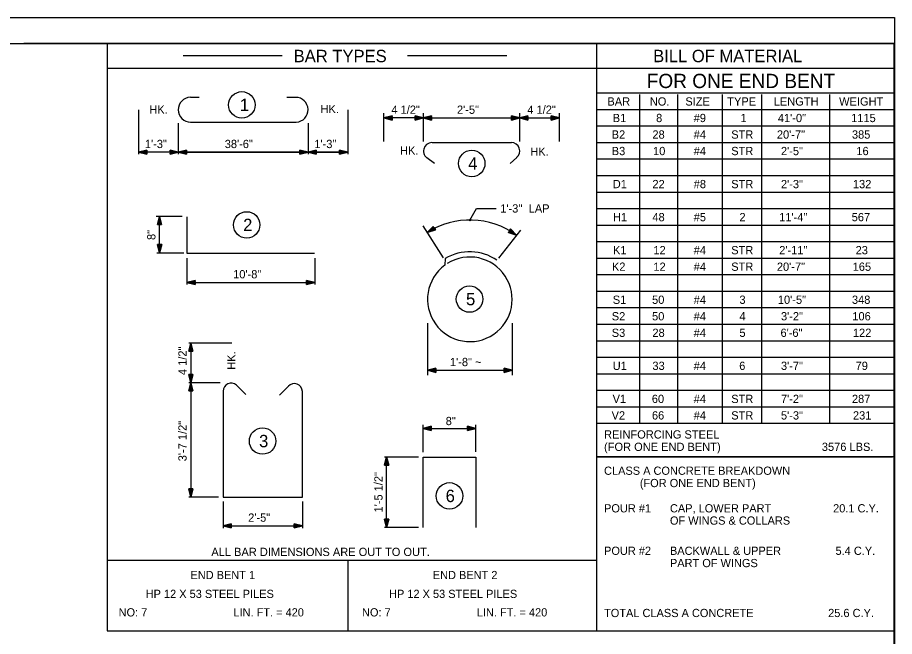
# Model space of a CAD drawing. Extents: x -41 to 251, y -169 to 237.
# Drawn here: x 45.29 to 75.65, y -139.61 to -118.18 of the extents above; entities that cross this region are included whole.
import ezdxf

# ---------------------------------------------------------------- set-up
doc = ezdxf.new("R2010")
doc.units = 0
for name, color, linetype in [('Dimension Lines CELL', 7, 'Continuous'), ('Plan Sheet CELL', 7, 'Continuous'), ('Plot Shape CELL', 7, 'Continuous'), ('Rebar Lines CELL', 7, 'Continuous'), ('Subtitle Text', 7, 'Continuous'), ('Text', 7, 'Continuous'), ('Text CELL', 7, 'Continuous')]:
    doc.layers.add(name, color=color, linetype=linetype)

msp = doc.modelspace()

# ---------------------------------------------------------------- linework, layer by layer
at = {"layer": 'Dimension Lines CELL'}
for p, q in [((49.476, -121.372), (49.476, -122.914)), ((56.718, -121.372), (56.718, -122.914)), ((57.969, -122.469), (57.969, -121.491)), ((59.336, -121.656), (57.969, -121.656)), ((59.336, -121.656), (62.673, -121.656)), ((59.342, -122.469), (59.342, -121.491)), ((62.673, -122.469), (62.673, -121.491)), ((62.673, -121.656), (64.046, -121.656)), ((64.046, -122.469), (64.046, -121.491)), ((50.849, -121.84), (50.849, -122.914)), ((55.345, -121.84), (55.345, -122.914)), ((50.853, -122.842), (49.476, -122.842)), ((50.853, -122.842), (55.345, -122.842)), ((56.489, -122.842), (50.853, -122.842)), ((55.345, -122.842), (56.718, -122.842)), ((50.983, -125.063), (50.087, -125.064)), ((50.205, -126.327), (50.204, -125.064)), ((60.947, -125.19), (61.175, -124.793)), ((61.175, -124.793), (61.862, -124.793)), ((60.031, -126.493), (59.334, -125.395)), ((62.699, -125.545), (61.939, -126.515)), ((50.107, -126.327), (51.045, -126.326)), ((51.146, -126.511), (51.146, -127.423)), ((55.576, -126.511), (55.576, -127.423)), ((51.146, -127.352), (55.576, -127.352)), ((59.482, -128.766), (59.482, -130.56)), ((62.411, -128.766), (62.411, -130.56)), ((52.707, -129.449), (51.213, -129.449)), ((51.284, -129.449), (51.284, -130.822)), ((59.487, -130.391), (62.416, -130.391)), ((52.308, -130.822), (51.213, -130.822)), ((51.284, -130.822), (51.284, -134.786)), ((59.327, -133.224), (59.327, -132.281)), ((61.157, -133.216), (61.157, -132.281)), ((59.327, -132.402), (61.157, -132.402)), ((59.174, -133.399), (57.995, -133.399)), ((58.067, -135.831), (58.067, -133.399)), ((52.25, -134.786), (51.213, -134.786)), ((52.403, -134.939), (52.403, -135.854)), ((55.148, -134.939), (55.148, -135.854)), ((52.403, -135.778), (55.148, -135.778)), ((59.174, -135.837), (57.995, -135.837))]:
    msp.add_line(p, q, dxfattribs=at)
for points in [[(58.255, -121.656), (58.255, -121.67), (57.969, -121.656), (58.255, -121.685), (58.255, -121.699), (57.969, -121.656), (58.255, -121.713), (58.255, -121.728), (57.969, -121.656), (58.255, -121.585), (58.255, -121.599), (57.969, -121.656), (58.255, -121.613), (58.255, -121.627), (57.969, -121.656), (58.255, -121.642), (58.255, -121.728), (58.255, -121.585), (57.969, -121.656), (58.255, -121.728)], [(59.05, -121.656), (59.05, -121.642), (59.336, -121.656), (59.05, -121.627), (59.05, -121.613), (59.336, -121.656), (59.05, -121.599), (59.05, -121.585), (59.336, -121.656), (59.05, -121.728), (59.05, -121.713), (59.336, -121.656), (59.05, -121.699), (59.05, -121.685), (59.336, -121.656), (59.05, -121.67), (59.05, -121.585), (59.05, -121.728), (59.336, -121.656), (59.05, -121.585)], [(59.622, -121.656), (59.622, -121.67), (59.336, -121.656), (59.622, -121.685), (59.622, -121.699), (59.336, -121.656), (59.622, -121.713), (59.622, -121.728), (59.336, -121.656), (59.622, -121.585), (59.622, -121.599), (59.336, -121.656), (59.622, -121.613), (59.622, -121.627), (59.336, -121.656), (59.622, -121.642), (59.622, -121.728), (59.622, -121.585), (59.336, -121.656), (59.622, -121.728)], [(62.387, -121.656), (62.387, -121.642), (62.673, -121.656), (62.387, -121.627), (62.387, -121.613), (62.673, -121.656), (62.387, -121.599), (62.387, -121.585), (62.673, -121.656), (62.387, -121.728), (62.387, -121.713), (62.673, -121.656), (62.387, -121.699), (62.387, -121.685), (62.673, -121.656), (62.387, -121.67), (62.387, -121.585), (62.387, -121.728), (62.673, -121.656), (62.387, -121.585)], [(62.959, -121.656), (62.959, -121.67), (62.673, -121.656), (62.959, -121.685), (62.959, -121.699), (62.673, -121.656), (62.959, -121.713), (62.959, -121.728), (62.673, -121.656), (62.959, -121.585), (62.959, -121.599), (62.673, -121.656), (62.959, -121.613), (62.959, -121.627), (62.673, -121.656), (62.959, -121.642), (62.959, -121.728), (62.959, -121.585), (62.673, -121.656), (62.959, -121.728)], [(63.76, -121.656), (63.76, -121.642), (64.046, -121.656), (63.76, -121.627), (63.76, -121.613), (64.046, -121.656), (63.76, -121.599), (63.76, -121.585), (64.046, -121.656), (63.76, -121.728), (63.76, -121.713), (64.046, -121.656), (63.76, -121.699), (63.76, -121.685), (64.046, -121.656), (63.76, -121.67), (63.76, -121.585), (63.76, -121.728), (64.046, -121.656), (63.76, -121.585)], [(49.762, -122.842), (49.762, -122.857), (49.476, -122.842), (49.762, -122.871), (49.762, -122.885), (49.476, -122.842), (49.762, -122.9), (49.762, -122.914), (49.476, -122.842), (49.762, -122.771), (49.762, -122.785), (49.476, -122.842), (49.762, -122.799), (49.762, -122.814), (49.476, -122.842), (49.762, -122.828), (49.762, -122.914), (49.762, -122.771), (49.476, -122.842), (49.762, -122.914)], [(50.567, -122.842), (50.567, -122.828), (50.853, -122.842), (50.567, -122.814), (50.567, -122.799), (50.853, -122.842), (50.567, -122.785), (50.567, -122.771), (50.853, -122.842), (50.567, -122.914), (50.567, -122.9), (50.853, -122.842), (50.567, -122.885), (50.567, -122.871), (50.853, -122.842), (50.567, -122.857), (50.567, -122.771), (50.567, -122.914), (50.853, -122.842), (50.567, -122.771)], [(51.139, -122.842), (51.139, -122.857), (50.853, -122.842), (51.139, -122.871), (51.139, -122.885), (50.853, -122.842), (51.139, -122.9), (51.139, -122.914), (50.853, -122.842), (51.139, -122.771), (51.139, -122.785), (50.853, -122.842), (51.139, -122.799), (51.139, -122.814), (50.853, -122.842), (51.139, -122.828), (51.139, -122.914), (51.139, -122.771), (50.853, -122.842), (51.139, -122.914)], [(55.059, -122.842), (55.059, -122.828), (55.345, -122.842), (55.059, -122.814), (55.059, -122.799), (55.345, -122.842), (55.059, -122.785), (55.059, -122.771), (55.345, -122.842), (55.059, -122.914), (55.059, -122.9), (55.345, -122.842), (55.059, -122.885), (55.059, -122.871), (55.345, -122.842), (55.059, -122.857), (55.059, -122.771), (55.059, -122.914), (55.345, -122.842), (55.059, -122.771)], [(55.631, -122.842), (55.631, -122.857), (55.345, -122.842), (55.631, -122.871), (55.631, -122.885), (55.345, -122.842), (55.631, -122.9), (55.631, -122.914), (55.345, -122.842), (55.631, -122.771), (55.631, -122.785), (55.345, -122.842), (55.631, -122.799), (55.631, -122.814), (55.345, -122.842), (55.631, -122.828), (55.631, -122.914), (55.631, -122.771), (55.345, -122.842), (55.631, -122.914)], [(56.432, -122.842), (56.432, -122.828), (56.718, -122.842), (56.432, -122.814), (56.432, -122.799), (56.718, -122.842), (56.432, -122.785), (56.432, -122.771), (56.718, -122.842), (56.432, -122.914), (56.432, -122.9), (56.718, -122.842), (56.432, -122.885), (56.432, -122.871), (56.718, -122.842), (56.432, -122.857), (56.432, -122.771), (56.432, -122.914), (56.718, -122.842), (56.432, -122.771)], [(50.204, -125.35), (50.19, -125.35), (50.204, -125.064), (50.176, -125.35), (50.161, -125.35), (50.204, -125.064), (50.147, -125.35), (50.133, -125.35), (50.204, -125.064), (50.276, -125.35), (50.262, -125.35), (50.204, -125.064), (50.247, -125.35), (50.233, -125.35), (50.204, -125.064), (50.219, -125.35), (50.133, -125.35), (50.276, -125.35), (50.204, -125.064), (50.133, -125.35)], [(59.718, -125.47), (59.726, -125.482), (59.474, -125.618), (59.733, -125.495), (59.74, -125.507), (59.474, -125.618), (59.748, -125.519), (59.755, -125.531), (59.474, -125.618), (59.681, -125.409), (59.689, -125.421), (59.474, -125.618), (59.696, -125.433), (59.703, -125.446), (59.474, -125.618), (59.711, -125.458), (59.755, -125.531), (59.681, -125.409), (59.474, -125.618), (59.755, -125.531)], [(62.321, -125.558), (62.328, -125.546), (62.56, -125.714), (62.336, -125.534), (62.344, -125.522), (62.56, -125.714), (62.352, -125.51), (62.359, -125.498), (62.56, -125.714), (62.282, -125.618), (62.289, -125.606), (62.56, -125.714), (62.297, -125.594), (62.305, -125.582), (62.56, -125.714), (62.313, -125.57), (62.359, -125.498), (62.282, -125.618), (62.56, -125.714), (62.359, -125.498)], [(50.205, -126.041), (50.219, -126.041), (50.205, -126.327), (50.234, -126.041), (50.248, -126.041), (50.205, -126.327), (50.262, -126.041), (50.277, -126.041), (50.205, -126.327), (50.133, -126.041), (50.148, -126.041), (50.205, -126.327), (50.162, -126.041), (50.176, -126.041), (50.205, -126.327), (50.191, -126.041), (50.277, -126.041), (50.133, -126.041), (50.205, -126.327), (50.277, -126.041)], [(51.432, -127.352), (51.432, -127.366), (51.146, -127.352), (51.432, -127.38), (51.432, -127.395), (51.146, -127.352), (51.432, -127.409), (51.432, -127.423), (51.146, -127.352), (51.432, -127.28), (51.432, -127.295), (51.146, -127.352), (51.432, -127.309), (51.432, -127.323), (51.146, -127.352), (51.432, -127.338), (51.432, -127.423), (51.432, -127.28), (51.146, -127.352), (51.432, -127.423)], [(55.29, -127.352), (55.29, -127.338), (55.576, -127.352), (55.29, -127.323), (55.29, -127.309), (55.576, -127.352), (55.29, -127.295), (55.29, -127.28), (55.576, -127.352), (55.29, -127.423), (55.29, -127.409), (55.576, -127.352), (55.29, -127.395), (55.29, -127.38), (55.576, -127.352), (55.29, -127.366), (55.29, -127.28), (55.29, -127.423), (55.576, -127.352), (55.29, -127.28)], [(51.284, -129.735), (51.27, -129.735), (51.284, -129.449), (51.256, -129.735), (51.241, -129.735), (51.284, -129.449), (51.227, -129.735), (51.213, -129.735), (51.284, -129.449), (51.356, -129.735), (51.341, -129.735), (51.284, -129.449), (51.327, -129.735), (51.313, -129.735), (51.284, -129.449), (51.299, -129.735), (51.213, -129.735), (51.356, -129.735), (51.284, -129.449), (51.213, -129.735)], [(51.284, -130.536), (51.299, -130.536), (51.284, -130.822), (51.313, -130.536), (51.327, -130.536), (51.284, -130.822), (51.341, -130.536), (51.356, -130.536), (51.284, -130.822), (51.213, -130.536), (51.227, -130.536), (51.284, -130.822), (51.241, -130.536), (51.256, -130.536), (51.284, -130.822), (51.27, -130.536), (51.356, -130.536), (51.213, -130.536), (51.284, -130.822), (51.356, -130.536)], [(59.773, -130.391), (59.773, -130.406), (59.487, -130.391), (59.773, -130.42), (59.773, -130.434), (59.487, -130.391), (59.773, -130.449), (59.773, -130.463), (59.487, -130.391), (59.773, -130.32), (59.773, -130.334), (59.487, -130.391), (59.773, -130.348), (59.773, -130.363), (59.487, -130.391), (59.773, -130.377), (59.773, -130.463), (59.773, -130.32), (59.487, -130.391), (59.773, -130.463)], [(62.13, -130.391), (62.13, -130.377), (62.416, -130.391), (62.13, -130.363), (62.13, -130.348), (62.416, -130.391), (62.13, -130.334), (62.13, -130.32), (62.416, -130.391), (62.13, -130.463), (62.13, -130.449), (62.416, -130.391), (62.13, -130.434), (62.13, -130.42), (62.416, -130.391), (62.13, -130.406), (62.13, -130.32), (62.13, -130.463), (62.416, -130.391), (62.13, -130.32)], [(51.284, -131.108), (51.27, -131.108), (51.284, -130.822), (51.256, -131.108), (51.241, -131.108), (51.284, -130.822), (51.227, -131.108), (51.213, -131.108), (51.284, -130.822), (51.356, -131.108), (51.341, -131.108), (51.284, -130.822), (51.327, -131.108), (51.313, -131.108), (51.284, -130.822), (51.299, -131.108), (51.213, -131.108), (51.356, -131.108), (51.284, -130.822), (51.213, -131.108)], [(59.613, -132.402), (59.613, -132.416), (59.327, -132.402), (59.613, -132.43), (59.613, -132.444), (59.327, -132.402), (59.613, -132.459), (59.613, -132.473), (59.327, -132.402), (59.613, -132.33), (59.613, -132.344), (59.327, -132.402), (59.613, -132.359), (59.613, -132.373), (59.327, -132.402), (59.613, -132.387), (59.613, -132.473), (59.613, -132.33), (59.327, -132.402), (59.613, -132.473)], [(60.871, -132.402), (60.871, -132.387), (61.157, -132.402), (60.871, -132.373), (60.871, -132.359), (61.157, -132.402), (60.871, -132.344), (60.871, -132.33), (61.157, -132.402), (60.871, -132.473), (60.871, -132.459), (61.157, -132.402), (60.871, -132.444), (60.871, -132.43), (61.157, -132.402), (60.871, -132.416), (60.871, -132.33), (60.871, -132.473), (61.157, -132.402), (60.871, -132.33)], [(58.067, -133.676), (58.052, -133.676), (58.067, -133.39), (58.038, -133.676), (58.024, -133.676), (58.067, -133.39), (58.009, -133.676), (57.995, -133.676), (58.067, -133.39), (58.138, -133.676), (58.124, -133.676), (58.067, -133.39), (58.109, -133.676), (58.095, -133.676), (58.067, -133.39), (58.081, -133.676), (57.995, -133.676), (58.138, -133.676), (58.067, -133.39), (57.995, -133.676)], [(51.284, -134.5), (51.299, -134.5), (51.284, -134.786), (51.313, -134.5), (51.327, -134.5), (51.284, -134.786), (51.341, -134.5), (51.356, -134.5), (51.284, -134.786), (51.213, -134.5), (51.227, -134.5), (51.284, -134.786), (51.241, -134.5), (51.256, -134.5), (51.284, -134.786), (51.27, -134.5), (51.356, -134.5), (51.213, -134.5), (51.284, -134.786), (51.356, -134.5)], [(52.689, -135.778), (52.689, -135.792), (52.403, -135.778), (52.689, -135.806), (52.689, -135.821), (52.403, -135.778), (52.689, -135.835), (52.689, -135.849), (52.403, -135.778), (52.689, -135.706), (52.689, -135.72), (52.403, -135.778), (52.689, -135.735), (52.689, -135.749), (52.403, -135.778), (52.689, -135.763), (52.689, -135.849), (52.689, -135.706), (52.403, -135.778), (52.689, -135.849)], [(54.862, -135.778), (54.862, -135.763), (55.148, -135.778), (54.862, -135.749), (54.862, -135.735), (55.148, -135.778), (54.862, -135.72), (54.862, -135.706), (55.148, -135.778), (54.862, -135.849), (54.862, -135.835), (55.148, -135.778), (54.862, -135.821), (54.862, -135.806), (55.148, -135.778), (54.862, -135.792), (54.862, -135.706), (54.862, -135.849), (55.148, -135.778), (54.862, -135.706)], [(58.067, -135.545), (58.081, -135.545), (58.067, -135.831), (58.095, -135.545), (58.109, -135.545), (58.067, -135.831), (58.124, -135.545), (58.138, -135.545), (58.067, -135.831), (57.995, -135.545), (58.009, -135.545), (58.067, -135.831), (58.024, -135.545), (58.038, -135.545), (58.067, -135.831), (58.052, -135.545), (58.138, -135.545), (57.995, -135.545), (58.067, -135.831), (58.138, -135.545)]]:
    msp.add_lwpolyline(points, dxfattribs=at)
for centre, radius in [((53.053, -121.203), 0.458), ((61.012, -123.232), 0.458), ((53.22, -125.359), 0.458), ((60.948, -125.19), 0.0229), ((60.937, -127.926), 0.458), ((53.772, -132.841), 0.458), ((60.242, -134.74), 0.458)]:
    msp.add_circle(centre, radius, dxfattribs=at)
msp.add_arc((60.947, -127.935), 2.746, 54.0023, 122.4453, dxfattribs=at)
at = {"layer": 'Plan Sheet CELL'}
for p, q in [((75.648, -118.18), (75.648, -118.18)), ((2.412, -119.081), (75.628, -119.081)), ((75.628, -119.081), (45.504, -119.081)), ((48.387, -119.081), (48.387, -139.408)), ((65.332, -119.081), (65.332, -139.408)), ((75.628, -119.081), (75.628, -167.129)), ((75.628, -119.081), (75.628, -137.959)), ((54.448, -119.51), (51.016, -119.51)), ((62.224, -119.51), (58.792, -119.51)), ((65.332, -119.94), (48.387, -119.94)), ((75.628, -119.94), (65.332, -119.94)), ((75.628, -120.799), (65.332, -120.799)), ((66.82, -120.843), (66.82, -132.239)), ((68.135, -120.843), (68.135, -132.239)), ((69.68, -120.843), (69.68, -132.239)), ((71.044, -120.843), (71.044, -132.239)), ((73.399, -120.843), (73.399, -132.239)), ((75.628, -121.371), (65.332, -121.371)), ((75.628, -121.943), (65.332, -121.943)), ((75.628, -122.515), (65.332, -122.515)), ((75.628, -123.087), (65.332, -123.087)), ((75.628, -123.659), (65.332, -123.659)), ((75.628, -124.231), (65.332, -124.231)), ((75.628, -124.803), (65.332, -124.803)), ((75.628, -125.375), (65.332, -125.375)), ((75.628, -125.947), (65.332, -125.947)), ((75.628, -126.519), (65.332, -126.519)), ((75.628, -127.091), (65.332, -127.091)), ((75.628, -127.663), (65.332, -127.663)), ((75.628, -128.235), (65.332, -128.235)), ((75.628, -128.807), (65.332, -128.807)), ((75.628, -129.379), (65.332, -129.379)), ((75.628, -129.951), (65.332, -129.951)), ((75.628, -130.523), (65.332, -130.523)), ((75.628, -131.095), (65.332, -131.095)), ((75.628, -131.667), (65.332, -131.667)), ((75.628, -132.239), (65.332, -132.239)), ((75.628, -133.383), (65.332, -133.383)), ((65.332, -133.383), (75.577, -133.383)), ((48.4, -136.965), (65.332, -136.965)), ((48.4, -136.965), (64.128, -136.965)), ((56.727, -136.965), (56.727, -139.408)), ((48.387, -139.408), (75.648, -139.408))]:
    msp.add_line(p, q, dxfattribs=at)
at = {"layer": 'Plot Shape CELL'}
msp.add_lwpolyline([(0, -118.18), (75.648, -118.18), (75.648, -168.516), (0, -168.516)], close=True, dxfattribs=at)
at = {"layer": 'Rebar Lines CELL'}
for p, q in [((51.271, -120.942), (51.576, -120.942)), ((54.916, -120.943), (54.611, -120.943)), ((51.278, -121.8), (54.939, -121.8)), ((59.639, -122.504), (62.384, -122.504)), ((59.722, -123.236), (59.46, -123.038)), ((62.34, -123.236), (62.576, -123.02)), ((51.144, -125.075), (51.144, -126.338)), ((51.144, -126.338), (55.574, -126.338)), ((60.095, -126.525), (60.079, -126.755)), ((53.19, -131.233), (52.865, -130.908)), ((54.666, -130.944), (54.354, -131.256))]:
    msp.add_line(p, q, dxfattribs=at)
for points in [[(52.403, -131.116), (52.403, -134.786), (55.148, -134.786), (55.148, -131.121)], [(59.327, -135.837), (59.327, -133.397), (61.157, -133.397), (61.157, -135.837)]]:
    msp.add_lwpolyline(points, dxfattribs=at)
for centre, radius, start, end in [((51.278, -121.371), 0.429, 90.9575, 270), ((54.916, -121.372), 0.429, 272.972, 90), ((59.639, -122.801), 0.297, 91.6756, 242.6185), ((62.376, -122.801), 0.297, 309.3145, 88.3244), ((60.947, -127.935), 1.647, 55.2112, 121.1302), ((60.947, -127.935), 1.464, 126.3141, 122.4154), ((52.68, -131.116), 0.277, 48.347, 179.1529), ((54.872, -131.13), 0.277, 1.7953, 137.8717)]:
    msp.add_arc(centre, radius, start, end, dxfattribs=at)

# ---------------------------------------------------------------- texts
at = {"layer": 'Plan Sheet CELL'}
msp.add_text('BAR TYPES', height=0.429, dxfattribs=at).set_placement((54.848, -119.726))
at = {"layer": 'Subtitle Text'}
for s, height, p in [('BILL OF MATERIAL', 0.429, (67.294, -119.725)), ('FOR ONE END BENT', 0.49335, (67.071, -120.621)), ('1', 0.429, (52.985, -121.417)), ('4', 0.429, (60.89, -123.447)), ('2', 0.429, (53.098, -125.573)), ('5', 0.429, (60.815, -128.141)), ('3', 0.429, (53.65, -133.056)), ('6', 0.429, (60.109, -134.954))]:
    msp.add_text(s, height=height, dxfattribs=at).set_placement(p)
at = {"layer": 'Text'}
for s, height, p in [('BAR', 0.286, (65.71, -121.228)), ('NO.', 0.286, (67.178, -121.228)), ('SIZE', 0.286, (68.408, -121.228)), ('TYPE', 0.286, (69.859, -121.228)), ('LENGTH', 0.286, (71.469, -121.228)), ('WEIGHT', 0.286, (73.732, -121.228)), ('4 1/2"', 0.286, (58.23, -121.513)), ('2\'-5"', 0.286, (60.502, -121.513)), ('4 1/2"', 0.286, (62.937, -121.513)), ('B1', 0.286, (65.895, -121.8)), ('8', 0.286, (67.396, -121.8)), ('#9', 0.286, (68.697, -121.8)), ('1', 0.286, (70.317, -121.8)), ('41\'-0"', 0.286, (71.612, -121.8)), ('1115', 0.286, (74.149, -121.8)), ('B2', 0.286, (65.859, -122.372)), ('28', 0.286, (67.268, -122.372)), ('#4', 0.286, (68.698, -122.372)), ('STR', 0.286, (69.997, -122.372)), ('20\'-7"', 0.286, (71.578, -122.372)), ('385', 0.286, (74.176, -122.372)), ('1\'-3"', 0.286, (49.696, -122.699)), ('38\'-6"', 0.286, (52.461, -122.699)), ('1\'-3"', 0.286, (55.563, -122.699)), ('B3', 0.286, (65.859, -122.944)), ('10', 0.286, (67.289, -122.944)), ('#4', 0.286, (68.698, -122.944)), ('STR', 0.286, (69.997, -122.944)), ('2\'-5"', 0.286, (71.719, -122.944)), ('16', 0.286, (74.33, -122.944)), ('D1', 0.286, (65.895, -124.088)), ('22', 0.286, (67.268, -124.088)), ('#8', 0.286, (68.698, -124.088)), ('STR', 0.286, (69.997, -124.088)), ('2\'-3"', 0.286, (71.719, -124.088)), ('132', 0.286, (74.21, -124.088)), ('H1', 0.286, (65.903, -125.232)), ('48', 0.286, (67.268, -125.232)), ('#5', 0.286, (68.698, -125.232)), ('2', 0.286, (70.281, -125.232)), ('11\'-4"', 0.286, (71.658, -125.232)), ('567', 0.286, (74.168, -125.232)), ('K1', 0.286, (65.903, -126.376)), ('12', 0.286, (67.302, -126.376)), ('#4', 0.286, (68.698, -126.376)), ('STR', 0.286, (69.997, -126.376)), ('2\'-11"', 0.286, (71.658, -126.376)), ('23', 0.286, (74.304, -126.376)), ('K2', 0.286, (65.867, -126.948)), ('12', 0.286, (67.302, -126.948)), ('#4', 0.286, (68.698, -126.948)), ('STR', 0.286, (69.997, -126.948)), ('20\'-7"', 0.286, (71.578, -126.948)), ('165', 0.286, (74.202, -126.948)), ('10\'-8"', 0.286, (52.752, -127.209)), ('S1', 0.286, (65.896, -128.092)), ('50', 0.286, (67.256, -128.092)), ('#4', 0.286, (68.698, -128.092)), ('3', 0.286, (70.281, -128.092)), ('10\'-5"', 0.286, (71.612, -128.092)), ('348', 0.286, (74.176, -128.092)), ('S2', 0.286, (65.86, -128.664)), ('50', 0.286, (67.256, -128.664)), ('#4', 0.286, (68.698, -128.664)), ('4', 0.286, (70.281, -128.664)), ('3\'-2"', 0.286, (71.719, -128.664)), ('106', 0.286, (74.189, -128.664)), ('S3', 0.286, (65.86, -129.236)), ('28', 0.286, (67.268, -129.236)), ('#4', 0.286, (68.698, -129.236)), ('5', 0.286, (70.281, -129.236)), ('6\'-6"', 0.286, (71.703, -129.236)), ('122', 0.286, (74.21, -129.236)), ('1\'-8" ~', 0.286, (60.259, -130.248)), ('U1', 0.286, (65.894, -130.38)), ('33', 0.286, (67.268, -130.38)), ('#4', 0.286, (68.698, -130.38)), ('6', 0.286, (70.273, -130.38)), ('3\'-7"', 0.286, (71.719, -130.38)), ('79', 0.286, (74.303, -130.38)), ('V1', 0.286, (65.89, -131.524)), ('60', 0.286, (67.248, -131.524)), ('#4', 0.286, (68.698, -131.524)), ('STR', 0.286, (69.997, -131.524)), ('7\'-2"', 0.286, (71.719, -131.524)), ('287', 0.286, (74.176, -131.524)), ('8"', 0.286, (60.112, -132.291)), ('V2', 0.286, (65.854, -132.096)), ('66', 0.286, (67.252, -132.096)), ('#4', 0.286, (68.698, -132.096)), ('STR', 0.286, (69.997, -132.096)), ('5\'-3"', 0.286, (71.719, -132.096)), ('231', 0.286, (74.212, -132.096)), ('REINFORCING STEEL', 0.286, (65.594, -132.755)), ('(FOR ONE END BENT)', 0.286, (65.594, -133.184)), ('3576 LBS.', 0.286, (73.134, -133.184)), ('CLASS A CONCRETE BREAKDOWN', 0.28433, (65.594, -134.01)), ('(FOR ONE END BENT)', 0.28433, (66.832, -134.437)), ('POUR #1', 0.2843, (65.594, -135.312)), ('CAP, LOWER PART', 0.28433, (67.875, -135.312)), ('20.1 C.Y.', 0.2843, (73.524, -135.312)), ('2\'-5"', 0.286, (53.273, -135.635)), ('OF WINGS & COLLARS', 0.28433, (67.875, -135.736)), ('ALL BAR DIMENSIONS ARE OUT TO OUT.', 0.286, (51.997, -136.822)), ('POUR #2', 0.2843, (65.594, -136.782)), ('BACKWALL & UPPER', 0.28433, (67.875, -136.782)), ('5.4 C.Y.', 0.2843, (73.608, -136.782)), ('PART OF WINGS', 0.28433, (67.875, -137.207)), ('END BENT 1', 0.2843, (51.273, -137.622)), ('END BENT 2', 0.2843, (59.663, -137.622)), ('HP 12 X 53 STEEL PILES', 0.28433, (49.723, -138.274)), ('HP 12 X 53 STEEL PILES', 0.28433, (58.149, -138.274)), ('NO: 7', 0.2843, (48.787, -138.914)), ('LIN. FT. = 420', 0.28433, (52.761, -138.914)), ('NO: 7', 0.2843, (57.213, -138.914)), ('LIN. FT. = 420', 0.28433, (61.187, -138.914)), ('TOTAL CLASS A CONCRETE', 0.28433, (65.594, -138.936)), ('25.6 C.Y.', 0.2843, (73.353, -138.936))]:
    msp.add_text(s, height=height, dxfattribs=at).set_placement(p)
for s, p in [('8"', (50.062, -125.882)), ('4 1/2"', (51.141, -130.557)), ('3\'-7 1/2"', (51.141, -133.541)), ('1\'-5 1/2"', (57.924, -135.314))]:
    msp.add_text(s, height=0.286, rotation=90, dxfattribs=at).set_placement(p)
at = {"layer": 'Text CELL'}
for s, p in [('HK.', (49.85, -121.508)), ('HK.', (55.778, -121.49)), ('HK.', (58.53, -122.927)), ('HK.', (63.04, -122.965)), ("1'-3''  LAP", (62, -124.932))]:
    msp.add_text(s, height=0.286, dxfattribs=at).set_placement(p)
msp.add_text('HK.', height=0.286, rotation=90, dxfattribs=at).set_placement((52.831, -130.373))

doc.saveas('drawing.dxf')
